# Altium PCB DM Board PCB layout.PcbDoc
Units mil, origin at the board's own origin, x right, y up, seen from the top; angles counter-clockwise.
Board outline 2298 x 2500 mil, 4 copper layers (Top Layer, InternalPlane1, InternalPlane2, Bottom Layer); 36 components, 42 nets, 176 pads, 73 vias.
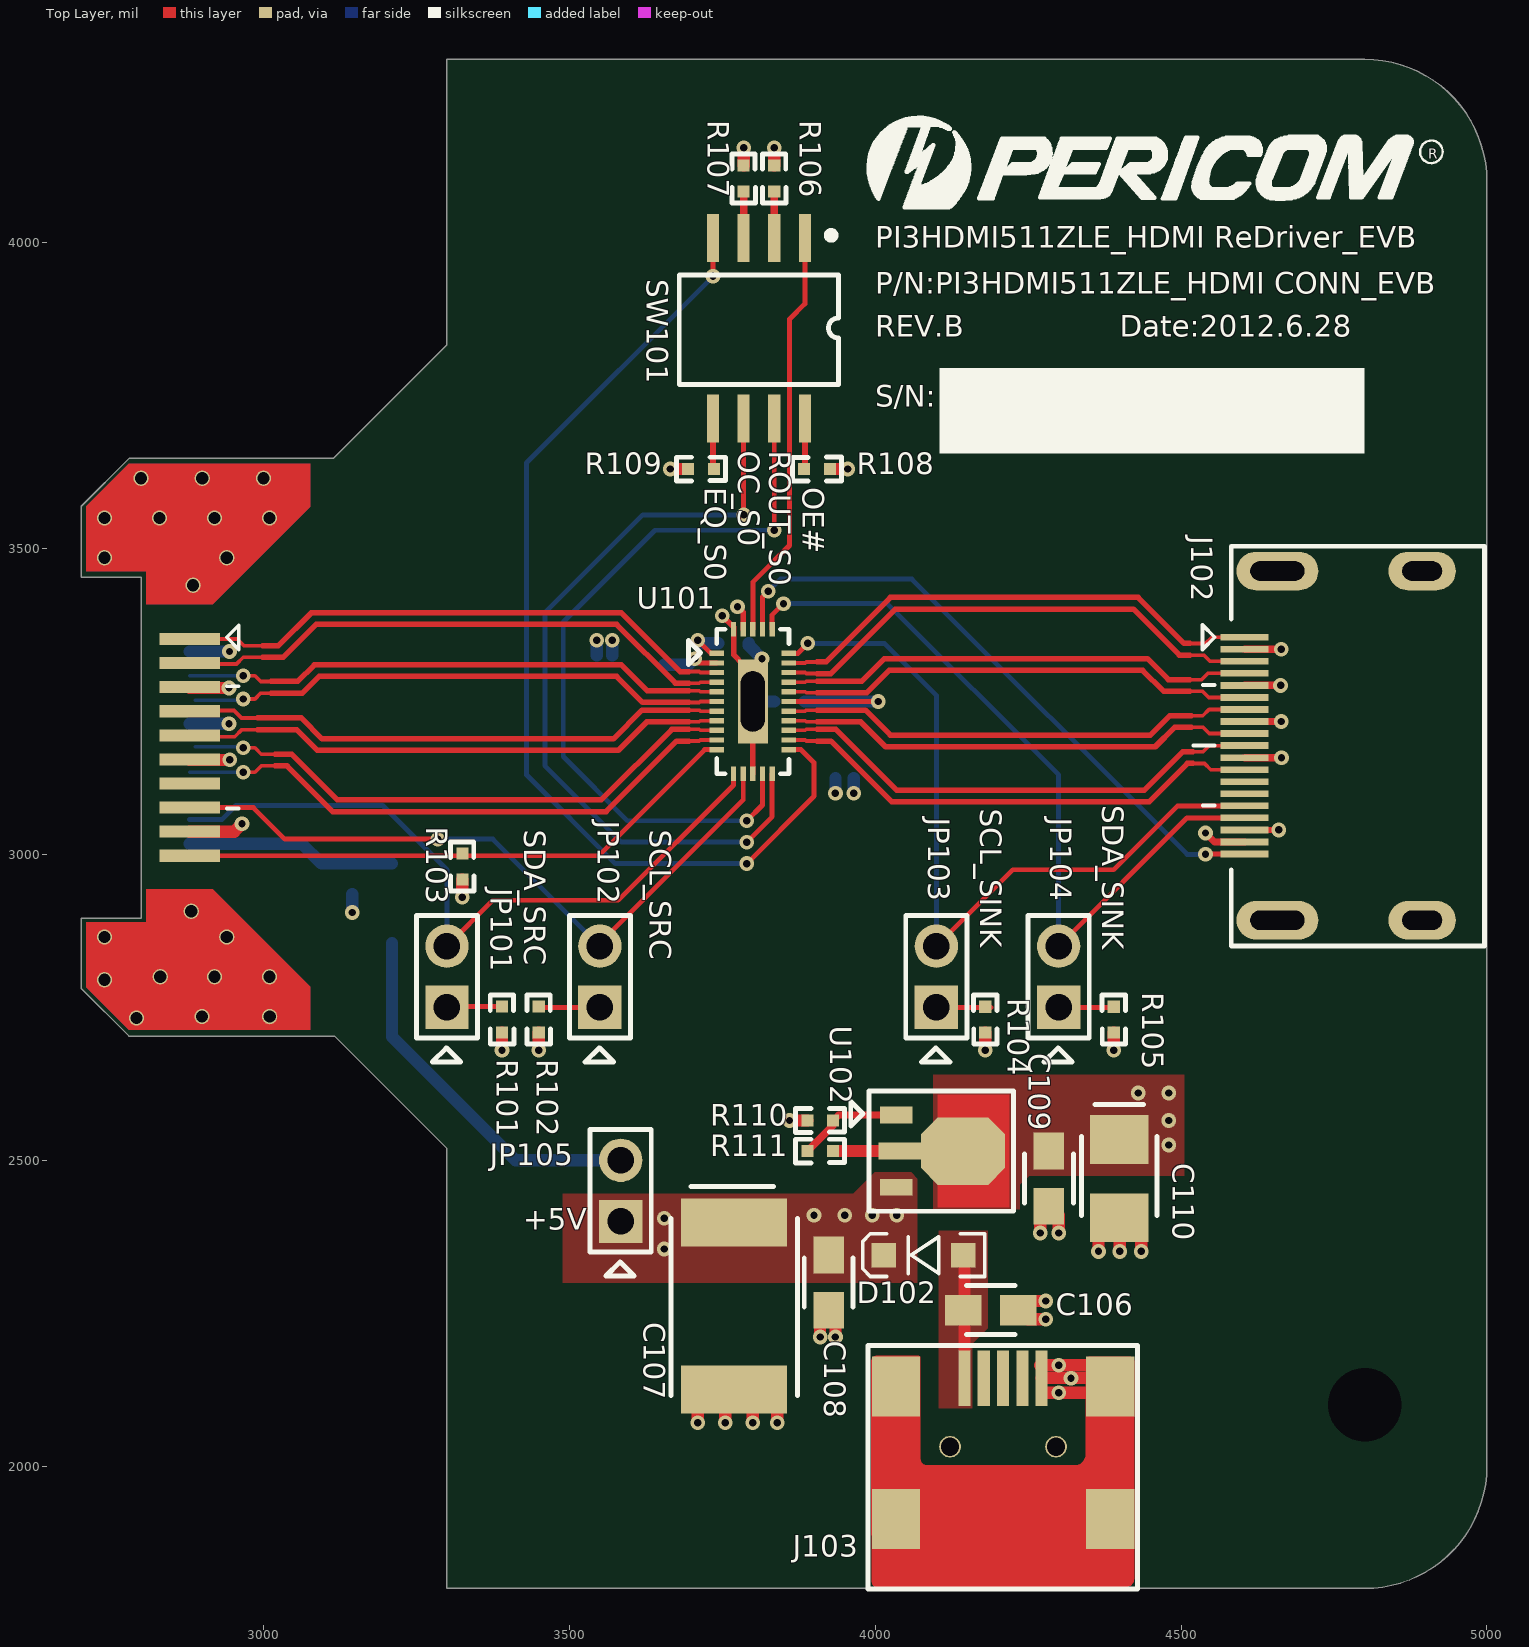
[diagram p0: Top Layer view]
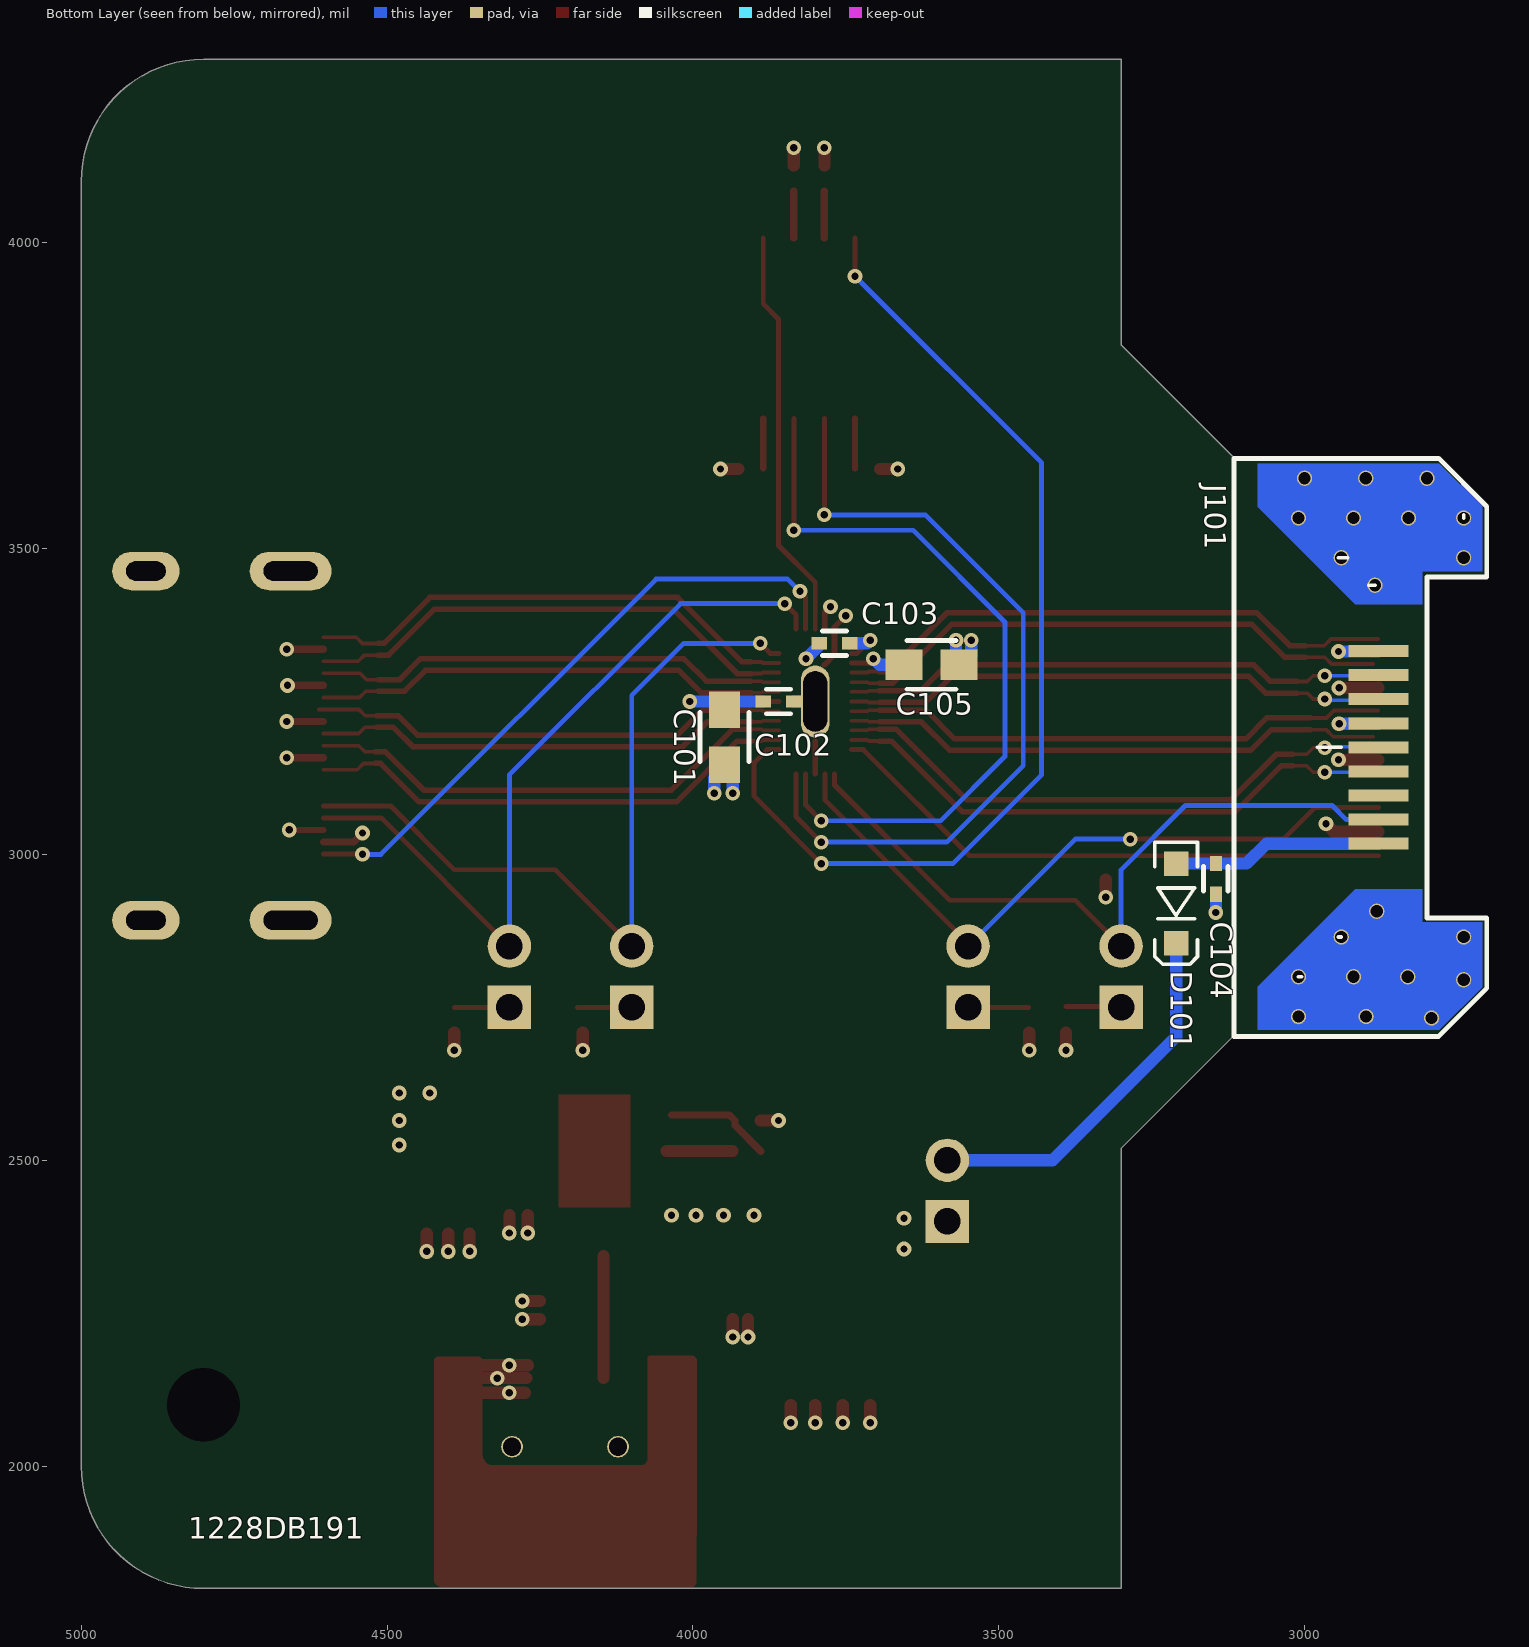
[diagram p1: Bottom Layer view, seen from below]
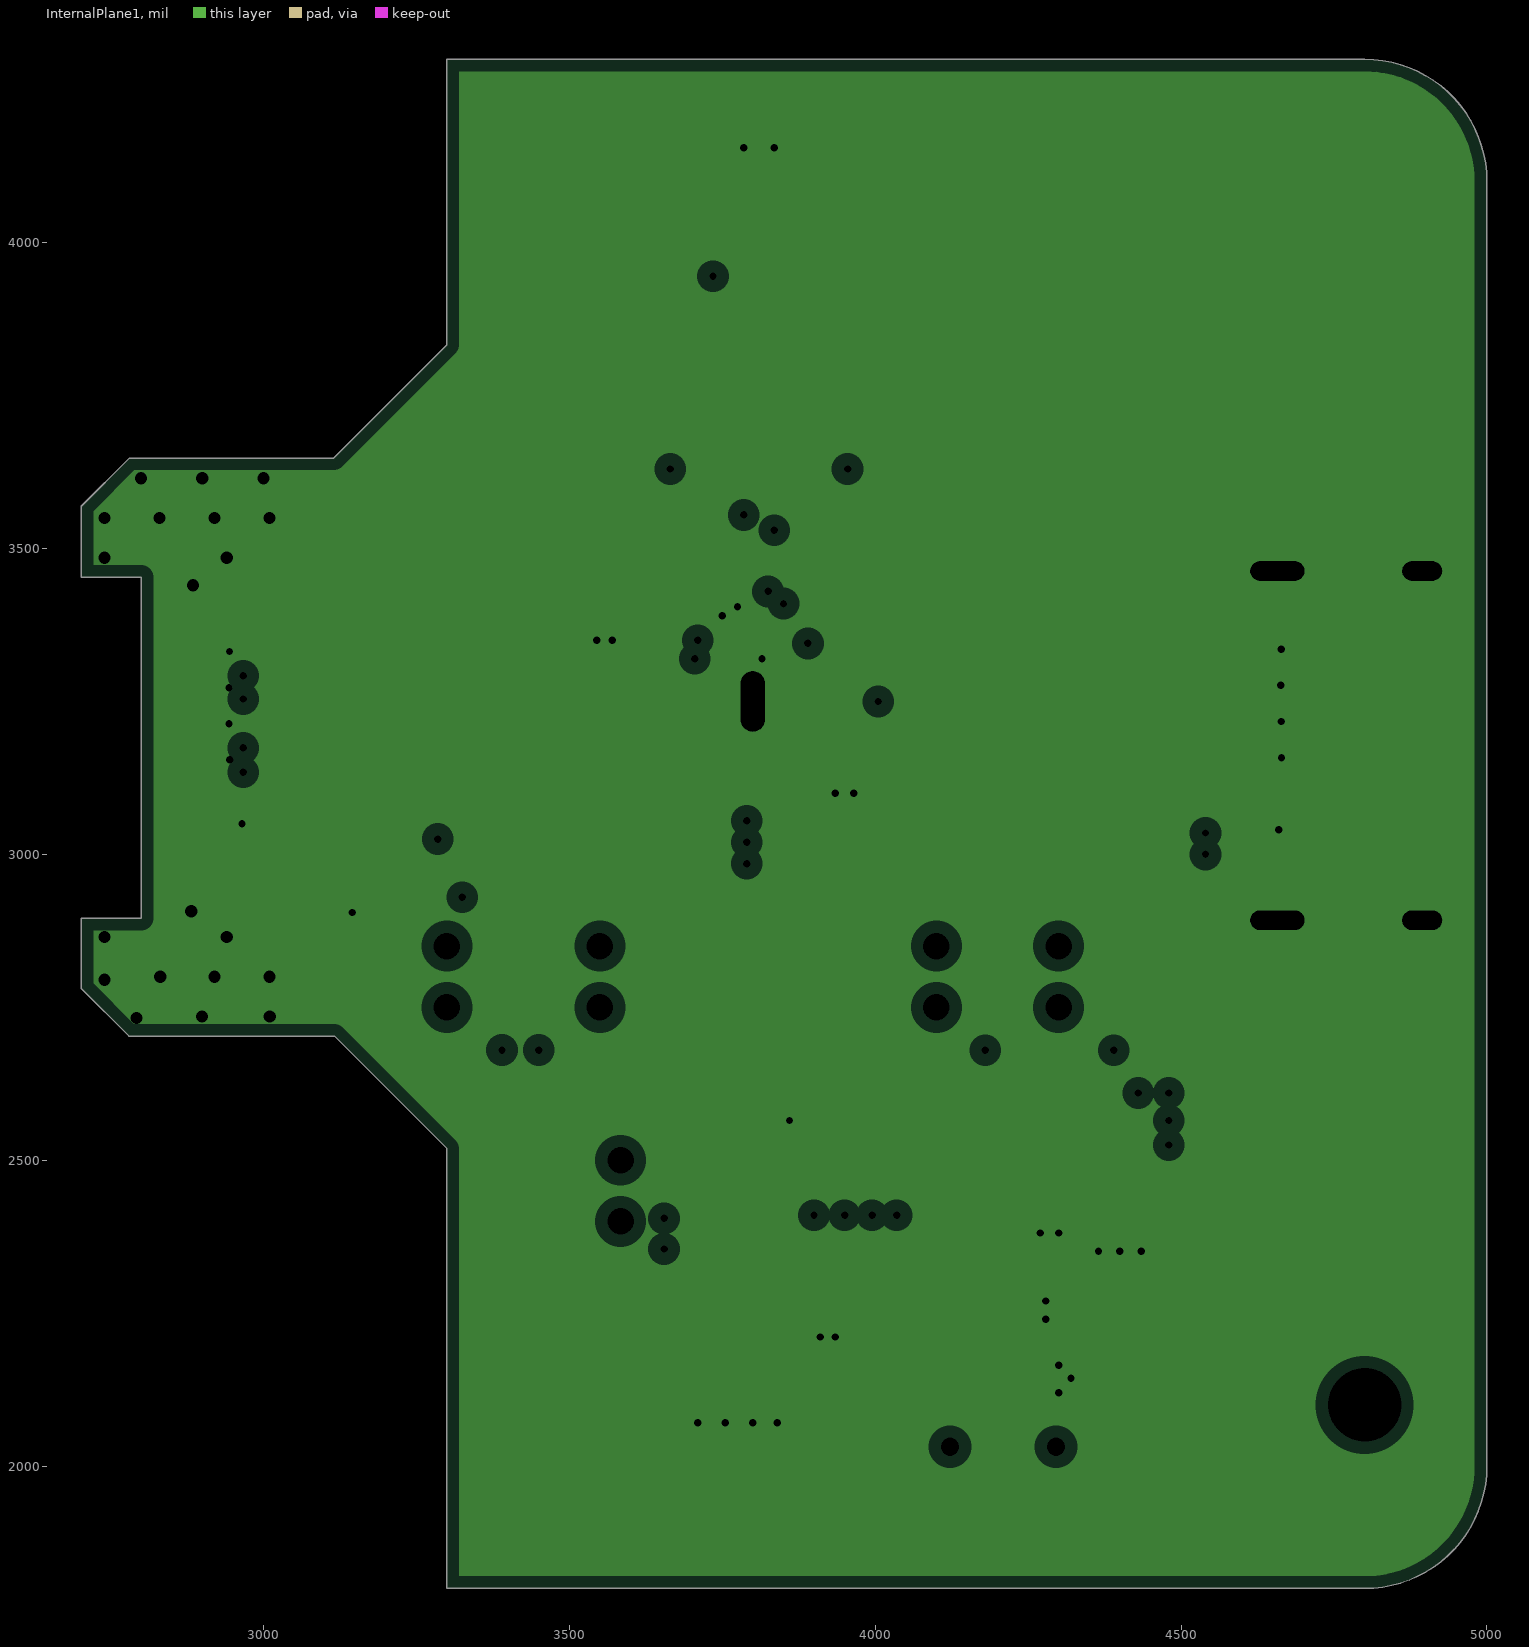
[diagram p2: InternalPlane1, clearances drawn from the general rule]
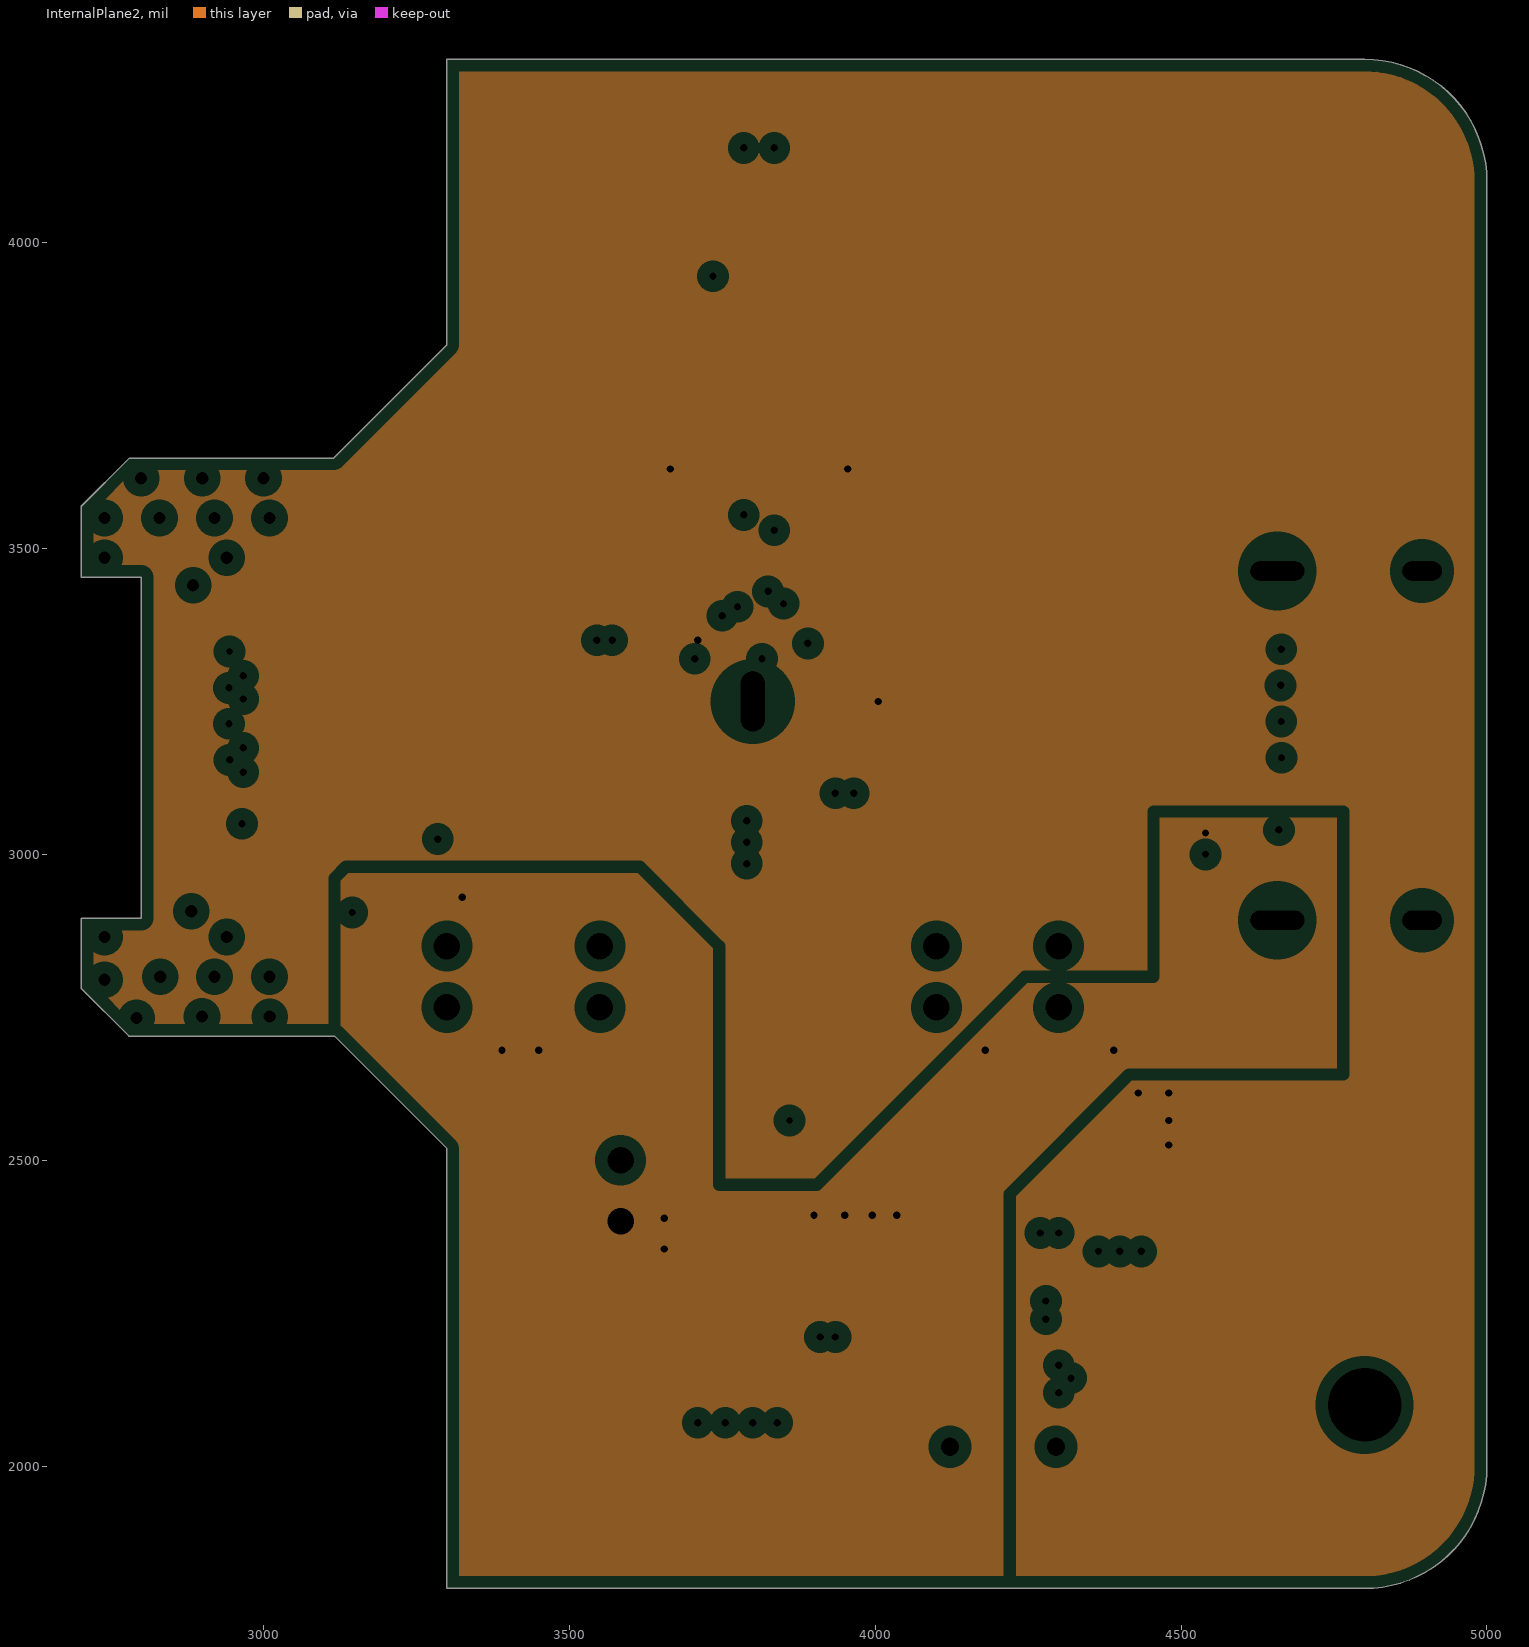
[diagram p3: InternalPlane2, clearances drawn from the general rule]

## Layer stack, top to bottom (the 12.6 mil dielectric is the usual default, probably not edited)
Top Layer: signal copper 1.4
Dielectric: core 12.6, FR-4, Dk 4.8
InternalPlane1: plane copper 1.4, net GND
Dielectric: prepreg 12.6, FR-4, Dk 4.8
InternalPlane2: plane copper 1.4, net (Multiple Nets)
Dielectric: core 12.6, FR-4, Dk 4.8
Bottom Layer: signal copper 1.4

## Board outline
2780,2703 2702,2781 2702,2896 2800,2896 2800,3453 2702,3453 2702,3569 2781,3648 3115,3648 3300,3833 3300,4300 4800,4300 cw(c4800,4100) 5000,4100 5000,2000 cw(c4800,2000) 4800,1800 3300,1800 3300,2519 3116,2703

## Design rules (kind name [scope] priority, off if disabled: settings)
Clearance [All] p1: gap=3
ComponentClearance [All] p1: gap=0 collisioncheckmode=3 verticalgap=0
DiffPairsRouting [All] p1: maxlimit=10 minlimit=10 mostfreqgap=10 maxuncoupledlength=500
HoleSize [All] p1: absolutevalues=TRUE maxlimit=500 minlimit=1 maxpercent=80.000 minpercent=20.000
PlaneClearance [All] p1: clearance=20
PlaneConnect [All] p1: planeconnectstyle=Direct reliefexpansion=20 reliefentries=4 reliefconductorwidth=10 reliefairgap=10
PolygonConnect [All] p1: connectstyle=Direct reliefconductorwidth=10 reliefentries=4 polygonreliefangle="90 Angle"
RoomDefinition "PI3HDMI511 EVB" [InComponentClass('PI3HDMI511 EVB')] p1: confinementstyle=ConfineIn formatcopy=TRUE lockcomponents=FALSE outline 15,185 17345,185 17345,7240 15,7240
RoutingVias [All] p1: holewidth=28 width=50 viastyle="Through Hole" minholewidth=8 minwidth=10 maxholewidth=28 maxwidth=50
SolderMaskExpansion [All] p1: expansion=4
TestPointUsage [All] p1: valid=0 allowmultiple=FALSE
Testpoint [All] p1: side=15 testpointundercomponent=TRUE minsize=40 maxsize=100 preferedsize=60 minholesize=0 maxholesize=40 preferedholesize=32 testpointgrid=1 style=1023 order=0123456789
Width [All] p1: maxlimit=150 minlimit=5 preferedwidth=10
14 further rules are at their usual default settings.

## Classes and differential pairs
component class "PI3HDMI511 EVB": C101 C102 C103 C104 C105 C106 C107 C108 C109 C110 D101 D102 J101 J102 J103 JP101 JP102 JP103 JP104 JP105 R101 R102 R103 R104 R105 R106 R107 R108 R109 R110 R111 SW101 U101 U102
differential pair NewDifferentialPair8: +OUT_D2- -OUT_D2+
differential pair NewDifferentialPair7: +OUT_D1- -OUT_D1+
differential pair NewDifferentialPair6: +OUT_D0- -OUT_D0+
differential pair NewDifferentialPair5: +OUT_CK- -OUT_CK+
differential pair NewDifferentialPair4: +IN_D2- -IN_D2+
differential pair NewDifferentialPair3: +IN_D1- -IN_D1+
differential pair NewDifferentialPair2: +IN_D0- -IN_D0+
differential pair NewDifferentialPair1: +IN_CK- -IN_CK+

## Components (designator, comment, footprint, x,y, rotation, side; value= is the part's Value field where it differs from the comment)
C101 "4.7u" CC_0805 3948.3,3191.7 r270 bottom
C102 "0.1u" CC_0402 3860,3250 r180 bottom
C103 "0.1u" CC_0402 3768.5,3345 r0 bottom
C104 "0.1u" CC_0402 3145,2960 r90 bottom
C105 "4.7u" CC_0805 3610,3310 r0 bottom
C106 "4.7u" CC_0805 4189,2255 r0 top
C107 "100u" CT_7343 3769,2280 r90 top
C108 "1u" CC_0805 3924,2300 r270 top
C109 "1u" CC_0805 4284,2470 r270 top
C110 "22u" CT_3528 4399,2470 r270 top
D101 "B0520LW" D@SOD-123 3210,2920 r270 bottom
D102 "B0520LW" D@SOD-123 4079,2345 r180 top
J101 "CON_HDMI_Plug" CON_HDMI_Plug 2840,3175 r0 bottom
J102 "CON_HDMI_Recept" CON_HDMI_Recept 4615,3355 r90 top
J103 "CON_USB2.0_MiniB_SMT" CON_USB2.0_MiniB_SMT 4209,1825 r90 top
JP101 "2x1 Pin Header" "2x1 Pin Header" 3300,2750 r90 top
JP102 "2x1 Pin Header" "2x1 Pin Header" 3550,2750 r90 top
JP103 "2x1 Pin Header" "2x1 Pin Header" 4100,2750 r90 top
JP104 "2x1 Pin Header" "2x1 Pin Header" 4300,2750 r90 top
JP105 "2x1 Pin Header" "2x1 Pin Header" 3584,2400 r90 top
R101 "47K" R_0402 3390,2730 r90 top
R102 "47K" R_0402 3450,2730 r90 top
R103 "4K7" R_0402 3325,2980 r90 top
R104 "2K2" R_0402 4180,2730 r270 top
R105 "2K2" R_0402 4390,2730 r270 top
R106 "4K7" R_0402 3835,4105 r90 top
R107 "4K7" R_0402 3785,4105 r90 top
R108 "4K7" R_0402 3905,3630 r180 top
R109 "4K7" R_0402 3715,3630 r0 top
R110 "0" RES@R_0402 3910,2565 r0 top
R111 "NP" RES@R_0402 3910,2515 r0 top
SW101 "SW_X4_Half_Pitch" SW_X4_Half_Pitch 3810,3860 r180 top
U101 "PI3HDMI511" TQFN32_3X6 3800,3250 r0 top locked
U102 "REG1117-3.3V" Pow_SOT_89 4089,2515 r270 top
? "" "Lable Hole" 4800,2100 r0 top
? "" PSC_LOG 4095,4160 r0 top

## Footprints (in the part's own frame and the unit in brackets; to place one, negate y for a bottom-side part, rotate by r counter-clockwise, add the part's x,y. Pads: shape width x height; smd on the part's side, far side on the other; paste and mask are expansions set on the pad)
"2x1 Pin Header" [mm] "Pin Header 2x1 Pitch 2.54mm"
  rect 1.8x1.8 hole 1.1: 1(0,0)
  round 1.8 hole 1.1: 2(2.54,0)
  silkscreen extent -2.27,-1.27 3.81,1.27
CC_0402 [mil]
  rect 25x20 smd: 1(-25,0) 2(25,0)
  silkscreen extent -20,-20 20,20
CC_0805 [mil]
  rect 60x50 smd: 1(-45,0) 2(45,0)
  silkscreen extent -40,-40 40,40
CON_HDMI_Plug [mm]
  rect 2.5x0.5 smd far side: 1(1,-4.5) 3(1,-3.5) 5(1,-2.5) 7(1,-1.5) 9(1,-0.5) 11(1,0.5) 13(1,1.5) 15(1,2.5) 17(1,3.5) 19(1,4.5)
  rect 2.5x0.5 smd: 2(1,-4) 4(1,-3) 6(1,-2) 8(1,-1) 10(1,0) 12(1,1) 14(1,2) 16(1,3) 18(1,4)
  round 0.635 hole 0.508: 20(-2.54,-9.525) 20(-2.54,-7.874) 20(-2.54,7.874) 20(-2.54,9.652) 20(-1.21,11.24) 20(-1.016,-11.176) 20(-0.254,-9.525) 20(-0.22,9.525) 20(1.067,6.807) 20(1.143,-6.731) 20(1.51,11.176) 20(1.524,-11.176) 20(2.032,-9.525) 20(2.032,9.525) 20(2.54,-7.874) 20(2.54,7.874) 20(4.064,-11.176) 20(4.318,-9.525) 20(4.318,9.525) 20(4.32,11.18)
  Top Layer region: -0.813,-5.944 1.968,-5.944 6.013,-9.989 6.013,-11.779 -1.517,-11.779 -1.524,-11.786 -3.302,-10.008 -3.302,-7.315 -0.813,-7.315
  Top Layer region: -0.813,5.893 1.968,5.893 6.013,9.938 6.013,11.728 -1.517,11.728 -1.524,11.735 -3.302,9.957 -3.302,7.264 -0.813,7.264
  Bottom Layer region: -0.813,-5.944 1.968,-5.944 6.013,-9.989 6.013,-11.779 -1.517,-11.779 -1.524,-11.786 -3.302,-10.008 -3.302,-7.315 -0.813,-7.315
  Bottom Layer region: -0.813,5.893 1.968,5.893 6.013,9.938 6.013,11.728 -1.517,11.728 -1.524,11.735 -3.302,9.957 -3.302,7.264 -0.813,7.264
  silkscreen extent -3.5,-12 7,12
CON_HDMI_Recept [mm]
  rect 0.28x2 smd: 1(0,0.281) 2(-0.5,0.281) 3(-1,0.281) 4(-1.5,0.281) 5(-2,0.281) 6(-2.5,0.281) 7(-3,0.281) 8(-3.5,0.281) 9(-4,0.281) 10(-4.5,0.281) 11(-5,0.281) 12(-5.5,0.281) 13(-6,0.281) 14(-6.5,0.281) 15(-7,0.281) 16(-7.5,0.281) 17(-8,0.281) 18(-8.5,0.281) 19(-9,0.281)
  oval 1.6x3.4 hole 0.8 slot 2.25 at 90 deg: 20(-11.75,-1.08) 21(2.75,-1.08)
  oval 1.6x2.8 hole 0.8 slot 1.65 at 90 deg: 22(-11.75,-7.09) 23(2.75,-7.09)
  silkscreen extent -12.82,-9.68 3.78,2.41
CON_USB2.0_MiniB_SMT [mm]
  rect 2.3x0.5 smd: 1(8.1,1.6) 2(8.1,0.8) 3(8.1,0) 4(8.1,-0.8) 5(8.1,-1.6)
  rect 2.5x2 smd: 5(2.25,4.45) 5(2.25,-4.45) 5(7.75,-4.45) 5(7.75,4.45)
  round 0.9 hole 0.762 unplated: 10(5.25,-2.2) 11(5.25,2.2)
  Top Layer region: 1.58,5.45 -0.35,5.45 -0.438,5.432 -0.513,5.383 -0.562,5.308 -0.58,5.22 -0.58,5.22 -0.58,-5.09 -0.553,-5.224 -0.477,-5.337 -0.364,-5.413 -0.23,-5.44 -0.23,-5.44 8.81,-5.44 8.875,-5.427 8.93,-5.39 8.967,-5.335 8.98,-5.27 8.98,-5.27 8.98,-3.59 8.968,-3.529 8.933,-3.477 8.881,-3.442 8.82,-3.43 8.82,-3.43 4.93,-3.43 4.758,-3.396 4.612,-3.298 4.514,-3.152 4.48,-2.98 4.48,-2.98 4.48,3.17 4.5,3.269 4.556,3.354 4.641,3.41 4.74,3.43 4.74,3.43 8.93,3.43 8.964,3.437 8.994,3.456 9.013,3.486 9.02,3.52 9.02,3.52 9.02,5.26 9.004,5.34 8.958,5.408 8.89,5.454 8.81,5.47 8.81,5.47 1.6,5.47 1.592,5.468 1.586,5.464 1.582,5.458 1.58,5.45
  silkscreen extent -0.65,-5.59 9.45,5.6
CT_3528 [mil]
  rect 80x95 smd: 1(-64,0) 2(64,0)
  silkscreen extent -121,-62 60,62
CT_7343 [mm]
  rect 2x4.4 smd: 1(3,0) 2(-3.926,-0.011)
  silkscreen extent -4.19,-2.64 4.5,2.62
D@SOD-123 [mil]
  rect 40x40 smd: 1(-65,0) 2(65,0)
  silkscreen extent -100,-35 100,35
"Lable Hole" [mil]
  round 0 hole 120 unplated: ""(0,0)
Pow_SOT_89 [mm] "SOT-89; Body 4.6 x 4.25 mm, inc. leads (LxW max)"
  rect 0.7x1.35 smd: 1(-1.5,-1.388) 3(1.5,-1.388)
  oct 2.8x3.5 smd: 2(0,1.388)
  rect 0.7x1.9 smd: 2(0,-1.163)
  Top Layer region: -2.346,0.336 -2.346,3.302 2.322,3.302 2.323,3.303 2.323,0.338 2.325,0.336
  silkscreen extent -2.5,-3.28 2.5,3.49
PSC_LOG [mil]
  silkscreen extent -107,-103 833,45
R_0402 [mm]
  rect 0.5x0.5 smd: 1(-0.532,-0.001) 2(0.54,-0.001)
  silkscreen extent -1.02,-0.49 1.02,0.49
RES@R_0402 [mm]
  rect 0.5x0.5 smd: 1(-0.532,-0.001) 2(0.54,-0.001)
  silkscreen extent -1.02,-0.49 1.02,0.49
SW_X4_Half_Pitch [mm]
  rect 0.5x2 smd: 1(-1.905,-3.75) 2(-0.635,-3.75) 3(0.635,-3.75) 4(1.905,-3.75) 5(1.905,3.75) 6(0.635,3.75) 7(-0.635,3.75) 8(-1.905,3.75)
  silkscreen extent -3.31,-4.01 3.31,2.34
TQFN32_3X6 [mm]
  rect 0.6x0.22 smd: 1(-1.5,2) 2(-1.5,1.6) 3(-1.5,1.2) 4(-1.5,0.8) 5(-1.5,0.4) 6(-1.5,0) 7(-1.5,-0.4) 8(-1.5,-0.8) 9(-1.5,-1.2) 10(-1.5,-1.6) 11(-1.5,-2) 17(1.5,-2) 18(1.5,-1.6) 19(1.5,-1.2) 20(1.5,-0.8) 21(1.5,-0.4) 22(1.5,0) 23(1.5,0.4) 24(1.5,0.8) 25(1.5,1.2) 26(1.5,1.6) 27(1.5,2)
  rect 0.22x0.6 smd: 12(-0.8,-3) 13(-0.4,-3) 14(0,-3) 15(0.4,-3) 16(0.8,-3) 28(0.8,3) 29(0.4,3) 30(0,3) 31(-0.4,3) 32(-0.8,3)
  rect 1.25x3.5 smd: 33(0,0)
  oval 1.2x3 hole 1 slot 2.5 at 90 deg: 33(0,0)
  silkscreen extent -2.67,-3 1.5,3

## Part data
C101 C102 C103: library part C_0.1u_0402
C104: library part C_10n_0402
C105: library part C_4.7u_0805
C106 C108 C109: library part "CHIP CAP0805"
C107: library part "100UF 7343_1"
C110: library part "22UF 3528"
D101 D102: library part SchottkyDiode@SOD-123_1
R101 R102 R103 R104 R105 R106 R107 R108 R109: library part R_0402
R110 R111: library part "CHIP RES0402_1"
U101: library part PI3VDP411LSZDE@TQFN48_4
U102: library part REG1117ADJ@SOT89

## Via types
v1: diameter 24, hole 12, Top Layer to Bottom Layer, tented both sides, 73 vias

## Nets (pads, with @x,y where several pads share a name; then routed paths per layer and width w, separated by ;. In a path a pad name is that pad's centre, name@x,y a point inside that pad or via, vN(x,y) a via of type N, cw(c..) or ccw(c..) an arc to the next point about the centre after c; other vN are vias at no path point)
+3V3: C101.1 C102.1 C103.1 C109.1 C110.1 R108.1 R109.1 R111.2 U101.1 U101.22 U102.2 | length 507.1
  Top Layer w8: v1(3710,3350) 3731.26,3328.74 U101.1 ; U101.22 v1(4005,3250)
  Top Layer w20: v1(3665.03,3629.97) R109.1 ; R108.1 v1(3954.97,3630.03) ; R111.2@3935.24,2515 U102.2@4043.21,2515
  Bottom Layer w20: v1@3710.2,3350 3715.2,3345 C103.1 ; C102.1 v1(4005,3250)
  other v1: 4480,2525 4480,2565 4430,2610 4480,2610
+5V: C107.1 C108.1 D102.2 J102.18 JP105.1 R101.1 R102.1 R103.1 R104.2 R105.2 U102.3 | length 215.1
  Top Layer w12: v1(4540,3035) 4554.65,3020.35 J102.18
  Top Layer w20: v1(3325.03,2930.03) R103.1 ; v1(3390.03,2680.03) R101.1 ; v1(3450.03,2680.03) R102.1 ; v1(4179.97,2679.72) R104.2 ; v1(4389.97,2679.72) R105.2
  other v1: 3655,2355 3655,2405 3900,2410 3950,2410 3995,2410 4035,2410
+5V_A: C104.2 D101.1 J101.18 | length 344.1
  Bottom Layer w20: J101.18 3062.48,3017.52 3095,2985 D101.1
+5V_USB: C106.1 D102.1 J103.1 | length 199.1
  Top Layer w20: J103.1 D102.1@4146.01,2342.99
/OE: SW101.1 U101.30 | length 674.7
  Top Layer w8: U101.30 3800,3445 3860,3505 3860,3875 3885,3900 SW101.1
EQ_S0: SW101.4 U101.17 | length 1684.3
  Top Layer w8: v1(3735,3945) SW101.4 ; v1(3790,2985) 3900,3095 3900,3150 3878.74,3171.26 U101.17
  Bottom Layer w8: v1(3735,3945) 3430,3640 3430,3130 3575,2985 v1(3790,2985)
GND: C101.2 C102.2 C103.2 C104.1 C105.1 C106.2 C107.2 C108.2 C109.2 C110.2 J101.2 J101.5 J101.8 J101.11 J101.17 J101.20 J102.2 J102.5 J102.8 J102.11 J102.17 J102.20 J102.21 J102.22 J102.23 J103.5 R106.2 R107.2 R110.1 U101.14 U101.31 U101.32 U101.33 | length 1726.7
  Top Layer w9: v1(3750,3390) 3768.5,3371.5 3768.5,3326.5 U101.33@3785,3310 ; v1(3775,3405) 3784.25,3395.75 U101.31 ; U101.14 U101.33@3800,3185
  Top Layer w10: J102.17 v1(4659.96,3040.04)
  Top Layer w12: J102.11 v1(4664.15,3158.15) ; J102.8 v1(4663.8,3217.2) ; J102.5 v1(4662.74,3276.26) ; J102.2 v1(4663.69,3335.32)
  Top Layer w20: J101.17 2952.2,3037.2 v1(2965,3050) ; J101.11@2879.37,3154.48 v1(2944.68,3154.48) ; J101.5@2879.37,3272.59 v1@2943,3272.17 ; v1(3710,2070.98) C107.2@3710,2100 ; v1(3755,2070.98) C107.2@3755,2100 ; R107.2 v1(3785.03,4154.97) ; v1(3800,2070.98) C107.2@3800,2100 ; R106.2 v1(3835.03,4154.97) ; v1(3840,2070.98) C107.2@3840,2100 ; v1(3860.03,2564.97) R110.1 ; v1(3910,2210.98) C108.2@3910,2240 ; v1(3935,2210.98) C108.2@3935,2240 ; C106.2@4250,2240 v1(4279.02,2240) ; C106.2@4250,2270 v1(4279.02,2270) ; J103.5@4270,2165 J103.5@4355,2165 ; v1(4270,2380.98) C109.2@4270,2410 ; J103.5@4271.99,2143.9 J103.5@4353.9,2143.9 ; J103.5@4275,2120 J103.5@4360,2120 ; v1(4300,2380.98) C109.2@4300,2410 ; v1(4365,2350.98) C110.2@4365,2380 ; v1(4400,2350.98) C110.2@4400,2380 ; v1(4435,2350.98) C110.2@4435,2380
  Bottom Layer w20: J101.8@2879.37,3213.54 v1(2943.63,3213.54) ; J101.2@2879.37,3331.65 v1(2944.48,3331.65) ; v1(3145,2905) C104.1 ; C105.1@3545,3325 v1(3545,3350) ; C105.1@3570,3325 v1(3570,3350) ; C103.2 3793.5,3341.5 v1(3815,3320) ; U101.33@3820,3250 C102.2 ; v1(3935,3100) C101.2@3935,3125 ; v1(3965,3100) C101.2@3965,3125
  other v1: 4300,2120 4320,2143.9 4300,2165 2943.63,3272.16
HPD_SINK: J102.19 U101.29 | length 1038.7
  Top Layer w8: U101.29 3815.75,3420.75 v1(3825,3430) ; v1@4540.67,3000.67 J102.19
  Bottom Layer w8: v1(3825,3430) 3845,3450 4060,3450 4510,3000 v1(4540,3000)
HPD_SRC: J101.19 R103.2 U101.11 | length 933.4
  Top Layer w8: J101.19 3547.83,2997.83 3721.26,3171.26 U101.11
IN_CK+: J101.10 U101.9 | length 936.5
  Top Layer w6: v1(2967,3174.17) 2986,3174.17 2996.5,3163.67 3019,3163.67 ; 3695.1,3204.38 3712.51,3204.38 3714.13,3202.76 U101.9
  Top Layer w9: 3019,3163.67 3046.33,3163.67 3121,3089 3552.13,3089 3667.51,3204.38 3695.1,3204.38
  Bottom Layer w6: J101.10@2889,3176.17 2965,3176.17 v1(2967,3174.17)
IN_CK-: J101.12 U101.10 | length 943.7
  Top Layer w6: v1(2967,3134.17) 2986,3134.17 2996.5,3144.67 3018,3144.67 ; 3694.92,3185.38 3712.51,3185.38 3714.13,3187.01 U101.10
  Top Layer w9: 3019,3144.67 3038.46,3144.67 3113.13,3070 3560,3070 3675.38,3185.38 3694.92,3185.38
  Bottom Layer w6: J101.12@2880,3134.17 v1(2967,3134.17)
IN_D0+: J101.7 U101.7 | length 900.8
  Top Layer w6: J101.7@2879.37,3235.17 2952,3235.17 2964.13,3223.04 2991,3223.04 ; 3695.1,3235.88 3712.51,3235.88 3714.13,3234.25 U101.7
  Top Layer w9: 2991,3223.04 3061.96,3223.04 3096,3189 3572.13,3189 3619.01,3235.88 3695.1,3235.88
IN_D0-: J101.9 U101.8 | length 894.1
  Top Layer w6: J101.9@2888,3192.17 2953,3192.17 2964.87,3204.04 2993,3204.04 ; 3694.92,3216.88 3712.51,3216.88 3714.13,3218.5 U101.8
  Top Layer w9: 2991,3204.04 3054.09,3204.04 3088.13,3170 3580,3170 3626.88,3216.88 3694.92,3216.88
IN_D1+: J101.4 U101.5 | length 895.2
  Top Layer w6: v1(2967,3292.17) 2986,3292.17 2995.5,3282.67 3013,3282.67 ; 3695.1,3267.37 3712.51,3267.37 3714.13,3265.75 U101.5
  Top Layer w9: 3013,3282.67 3055.8,3282.67 3083.13,3310 3585,3310 3627.63,3267.37 3695.1,3267.37
  Bottom Layer w6: J101.4@2879.37,3292.28 2879.48,3292.17 v1(2967,3292.17)
IN_D1-: J101.6 U101.6 | length 885.4
  Top Layer w6: v1(2967,3254.17) 2986,3254.17 2995.5,3263.67 3012,3263.67 ; 3694.92,3248.37 3712.51,3248.37 3714.13,3250 U101.6
  Top Layer w9: 3013,3263.67 3063.67,3263.67 3091,3291 3577.13,3291 3619.76,3248.37 3694.92,3248.37
  Bottom Layer w6: J101.6@2889,3252.17 2965,3252.17 v1(2967,3254.17)
IN_D2+: J101.1 U101.3 | length 928.9
  Top Layer w6: J101.1 2956.98,3352.17 2968,3341.15 2999,3341.15 ; 3695.1,3298.87 3712.51,3298.87 3714.13,3297.24 U101.3
  Top Layer w9: 2999,3341.15 3024.28,3341.15 3078.13,3395 3585,3395 3681.13,3298.87 3695.1,3298.87
IN_D2-: J101.3 U101.4 | length 920.3
  Top Layer w6: J101.3@2888,3311.17 2956.02,3311.17 2967,3322.15 2999,3322.15 ; 3694.92,3279.87 3712.51,3279.87 3714.13,3281.5 U101.4
  Top Layer w9: 2999,3322.15 3032.15,3322.15 3086,3376 3577.13,3376 3673.26,3279.87 3694.92,3279.87
NetC105_2: C105.2 U101.2 | length 93
  Top Layer w8: v1(3705,3320) 3712.01,3312.99 U101.2
  Bottom Layer w20: C105.2 3695,3310 v1(3705,3320)
NetD101_2: D101.2 JP105.2 | length 610.7
  Bottom Layer w20: D101.2 3210,2702 3412,2500 JP105.2
NetJP101_2: JP101.1 R101.2 | length 88.8
  Top Layer w8: JP101.1@3301.27,2751.27 R101.2
NetJP102_2: JP102.1 R102.2 | length 98.7
  Top Layer w8: R102.2@3451.3,2750 JP102.1
NetJP103_1: JP103.1 R104.1 | length 89
  Top Layer w8: JP103.1 R104.1@4189.02,2750
NetJP104_1: JP104.1 R105.1 | length 90
  Top Layer w8: JP104.1 R105.1@4389.97,2750
NetR106_1: R106.1 SW101.2 | length 76.4
  Top Layer w12: SW101.2 R106.1
NetR107_1: R107.1 SW101.3 | length 76.4
  Top Layer w12: SW101.3 R107.1
NetR108_2: R108.2 SW101.8 | length 81.1
  Top Layer w10: R108.2@3885,3631.3 SW101.8
NetR109_2: R109.2 SW101.5 | length 81.1
  Top Layer w10: R109.2@3735,3631.24 SW101.5
NetR110_2: R110.2 R111.1 U102.1 | length 174.4
  Top Layer w12: R111.1 3931.27,2557.19 R110.2 3940.35,2574.06 U102.1
OC_S0: SW101.6 U101.16 | length 1309.5
  Top Layer w8: v1(3785,3555) SW101.6 ; v1(3790,3020) 3831.5,3061.5 U101.16
  Bottom Layer w8: v1(3785,3555) 3620,3555 3460,3395 3460,3145 3585,3020 v1(3790,3020)
OUT_CK+: J102.10 U101.19 | length 816.9
  Top Layer w6: U101.19 3885.87,3202.76 3887.49,3204.38 3905.08,3204.38 ; 4519,3167.65 4536,3167.65 4546.18,3177.83 J102.10
  Top Layer w9: 3905.08,3204.38 3935.62,3204.38 4035,3105 4440,3105 4502.65,3167.65 4519,3167.65
OUT_CK-: J102.12 U101.18 | length 815.9
  Top Layer w6: U101.18 3885.87,3187.01 3887.49,3185.38 3904.9,3185.38 ; 4520,3148.65 4538.35,3148.65 4548.54,3138.46 J102.12
  Top Layer w9: 3904.9,3185.38 3927.75,3185.38 4027.13,3086 4447.87,3086 4510.52,3148.65 4519,3148.65
OUT_D0+: J102.7 U101.21 | length 787
  Top Layer w6: U101.21 3885.87,3234.25 3887.49,3235.88 3905.08,3235.88 ; 4517,3226.7 4535.7,3226.7 4545.89,3236.89 J102.7@4611.11,3236.89
  Top Layer w9: 3905.08,3235.88 3984.12,3235.88 4025,3195 4450,3195 4481.7,3226.7 4517,3226.7
OUT_D0-: J102.9 U101.20 | length 780.8
  Top Layer w6: U101.20 3885.87,3218.5 3887.49,3216.88 3904.9,3216.88 ; 4516,3207.7 4536,3207.7 4546.19,3197.52 J102.9
  Top Layer w9: 3904.9,3216.88 3976.25,3216.88 4017.13,3176 4457.87,3176 4489.57,3207.71 4517,3207.71
OUT_D1+: J102.4 U101.24 | length 779.2
  Top Layer w6: U101.24 3885.87,3281.5 3887.49,3283.12 3905.08,3283.12 ; 4514,3285.76 4534,3285.76 4544.19,3295.94 J102.4
  Top Layer w9: 3905.08,3283.12 3978.12,3283.12 4015,3320 4445,3320 4479.24,3285.76 4514,3285.76
OUT_D1-: J102.6 U101.23 | length 779.2
  Top Layer w6: U101.23 3885.87,3265.75 3887.49,3264.12 3904.9,3264.12 ; 4514,3266.76 4535,3266.76 4545.18,3256.57 J102.6
  Top Layer w9: 3904.9,3264.12 3985.99,3264.12 4022.87,3301 4437.13,3301 4471.37,3266.76 4514,3266.76
OUT_D2+: J102.1 U101.26 | length 824.6
  Top Layer w6: U101.26 3885.87,3312.99 3887.49,3314.62 3905.08,3314.62 ; 4514,3344.82 4540,3344.82 4550.18,3355 J102.1
  Top Layer w9: 3905.08,3314.62 3919.62,3314.62 4025,3420 4430,3420 4505.18,3344.82 4514,3344.82
OUT_D2-: J102.3 U101.25 | length 824.6
  Top Layer w6: U101.25 3885.87,3297.24 3887.49,3295.62 3904.9,3295.62 ; 4514,3325.81 4537,3325.81 4547.19,3315.63 J102.3
  Top Layer w9: 3904.9,3295.62 3927.49,3295.62 4032.87,3401 4422.13,3401 4497.31,3325.82 4514,3325.82
ROUT_S0: SW101.7 U101.15 | length 1240.5
  Top Layer w8: v1(3790,3055) 3815.75,3080.75 U101.15 ; v1(3835,3530) SW101.7
  Bottom Layer w8: v1(3790,3055) 3595,3055 3490,3160 3490,3380 3640,3530 v1(3835,3530)
SCL_SINK: J102.15 JP103.2 U101.27 | length 1291.8
  Top Layer w8: U101.27 3873.74,3328.74 v1(3890,3345) ; JP103.2 4225,2975 4390,2975 4494.41,3079.41 J102.15
  Bottom Layer w8: v1(3890,3345) 4015,3345 4100,3260 JP103.2
SCL_SRC: J101.15 JP102.2 U101.13 | length 1141.9
  Top Layer w8: J101.15 2983.43,3076.57 3035,3025 v1(3285,3025) ; JP102.2@3547.5,2852.5 3784.25,3089.25 U101.13
  Bottom Layer w8: v1(3285,3025) 3375,3025 JP102.2
SDA_SINK: J102.16 JP104.2 U101.28 | length 1286.3
  Top Layer w8: U101.28 3831.5,3391.5 v1(3850,3410) ; JP104.2 4509.72,3059.72 J102.16
  Bottom Layer w8: v1(3850,3410) 4020,3410 4300,3130 JP104.2
SDA_SRC: J101.16 JP101.2 U101.12 | length 1194.7
  Top Layer w8: JP101.2 3375,2925 3580,2925 3768.5,3113.5 U101.12
  Bottom Layer w8: J101.16 2931.89,3056.89 2955,3080 3195,3080 3300,2975 JP101.2
pads on no net: ?. J101.13 J101.14 J102.13 J102.14 J103.2 J103.3 J103.4 J103.10 J103.11

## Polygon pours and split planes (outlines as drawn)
+3V3 on Top Layer "MidLayer1-No Net" (solid, remove dead copper, pour order 1002): 4095,2640 4505,2640 4505,2475 4251.91,2475 4236.73,2460 4236.73,2420 4095,2420 4095,2640
+5V on Top Layer "MidLayer1-No Net" (solid, remove dead copper, pour order 1001): 3999,2480 4059,2480 4069,2470 4069,2300 3489,2300 3489,2445 3964,2445 3999,2480
+5V_USB on Top Layer "MidLayer1-No Net" (solid, remove dead copper, pour order 1000): 4159,2095 4104,2095 4104,2385 4184,2385 4184,2225 4159,2200 4159,2095
GND on InternalPlane1 (split plane): 4823.48,4278.35 4846.56,4273.76 4868.84,4266.19 4889.94,4255.78 4909.51,4242.71 4927.2,4227.2 4942.71,4209.51 4955.79,4189.94 4966.19,4168.84 4973.76,4146.56 4978.35,4123.48 4979.82,4101.05 4979.61,4100 4979.61,2000 4979.82,1998.95 4978.35,1976.52 4973.76,1953.44 4966.19,1931.16 4955.78,1910.06 4942.71,1890.49 4927.2,1872.8 4909.51,1857.29 4889.94,1844.21 4868.84,1833.81 4846.56,1826.24 4823.48,1821.65 4801.05,1820.18 4800,1820.39 3320.39,1820.39 3320.39,2519 3318.84,2526.8 3314.42,2533.42 3130.42,2717.42 3123.8,2721.84 3116,2723.39 2788.45,2723.39 2722.39,2789.45 2722.39,2875.61 2800,2875.61 2807.8,2877.16 2814.42,2881.58 2818.84,2888.2 2820.39,2896 2820.39,3453 2818.84,3460.8 2814.42,3467.42 2807.8,3471.84 2800,3473.39 2722.39,3473.39 2722.39,3560.55 2789.45,3627.61 3115,3627.61 3122.8,3629.16 3129.42,3633.58 3314.42,3818.58 3318.84,3825.2 3320.39,3833 3320.39,4279.61 4800,4279.61 4801.05,4279.82
+5V on InternalPlane2 (split plane): 4754.8,2650.2 4415,2650.2 4411.1,2649.42 4407.79,2647.21 4212.79,2452.21 4210.58,2448.9 4209.8,2445 4209.8,1820.39 3320.39,1820.39 3320.39,2519 3318.84,2526.8 3314.42,2533.42 3130.42,2717.42 3126.2,2720.24 3126.2,2956.78 3139.22,2969.8 3610.78,2969.8 3734.8,2845.78 3734.8,2460 3735.58,2456.1 3737.79,2452.79 3741.1,2450.58 3745,2449.8 3905,2449.8 3908.9,2450.58 3912.21,2452.79 4249.22,2789.8 4455,2789.8 4458.9,2790.58 4462.21,2792.79 4464.42,2796.1 4465.2,2800 4465.2,3059.8 4754.8,3059.8
+3V3 on InternalPlane2 (split plane): 4823.48,4278.35 4846.56,4273.76 4868.84,4266.19 4889.94,4255.78 4909.51,4242.71 4927.2,4227.2 4942.71,4209.51 4955.79,4189.94 4966.19,4168.84 4973.76,4146.56 4978.35,4123.48 4979.82,4101.05 4979.61,4100 4979.61,2000 4979.82,1998.95 4978.35,1976.52 4973.76,1953.44 4966.19,1931.16 4955.78,1910.06 4942.71,1890.49 4927.2,1872.8 4909.51,1857.29 4889.94,1844.21 4868.84,1833.81 4846.56,1826.24 4823.48,1821.65 4801.05,1820.18 4800,1820.39 4230.2,1820.39 4230.2,2440.78 4419.22,2629.8 4765,2629.8 4768.9,2630.58 4772.21,2632.79 4774.42,2636.1 4775.2,2640 4775.2,3070 4774.42,3073.9 4772.21,3077.21 4768.9,3079.42 4765,3080.2 4455,3080.2 4451.1,3079.42 4447.79,3077.21 4445.58,3073.9 4444.8,3070 4444.8,2810.2 4245,2810.2 4241.1,2809.42 4237.79,2807.21 3900.78,2470.2 3755.2,2470.2 3755.2,2850 3754.42,2853.9 3752.21,2857.21 3622.21,2987.21 3618.9,2989.42 3615,2990.2 3135,2990.2 3131.1,2989.42 3127.79,2987.21 3108.79,2968.21 3106.58,2964.9 3105.8,2961 3105.8,2723.39 2788.45,2723.39 2722.39,2789.45 2722.39,2875.61 2800,2875.61 2807.8,2877.16 2814.42,2881.58 2818.84,2888.2 2820.39,2896 2820.39,3453 2818.84,3460.8 2814.42,3467.42 2807.8,3471.84 2800,3473.39 2722.39,3473.39 2722.39,3560.55 2789.45,3627.61 3115,3627.61 3122.8,3629.16 3129.42,3633.58 3314.42,3818.58 3318.84,3825.2 3320.39,3833 3320.39,4279.61 4800,4279.61 4801.05,4279.82

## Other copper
Top Layer:
  text "TOP LAYER" at 6041,1991 h80
  text "1" at 6691,1861 h80
Bottom Layer:
  text "BOTTOM LAYER" at 6041,1991 h80
  text "4" at 6691,1861 h80
InternalPlane1 (plane layer: these items are gaps in the copper):
  text "POWER PLANE LAYER" at 6041,1991 h80
  text "2" at 6691,1861 h80
InternalPlane2 (plane layer: these items are gaps in the copper):
  lines w20: 3116,2703 3116,2961 3135,2980 3615,2980 3745,2850 3745,2460 3905,2460 4245,2800 4455,2800 4455,3070 4765,3070 4765,2640 4415,2640 4220,2445 4220,1800
  text "GND PLANE LAYER" at 6041,1991 h80
  text "3" at 6691,1861 h80

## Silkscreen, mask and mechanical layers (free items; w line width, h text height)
Top Overlay:
  rectangle: 4105,3655 4800,3795
  text "PI3HDMI511ZLE_HDMI ReDriver_EVB" at 4000,3980 h60
  text "P/N:PI3HDMI511ZLE_HDMI CONN_EVB" at 4000,3905 h60
  text "REV.B" at 4000,3835 h60
  text "Date:2012.6.28" at 4400,3835 h60
  text "S/N:" at 4000,3720 h60
  text "OC_S0" at 3765,3660 h60 r270
  text "ROUT_S0" at 3815,3660 h60 r270
  text "EQ_S0" at 3710,3600 h60 r270
  text "OE#" at 3870,3600 h60 r270
  text "SDA_SINK" at 4360,3080 h60 r270
  text "SCL_SINK" at 4160,3075 h60 r270
  text "SDA_SRC" at 3415,3040 h60 r270
  text "SCL_SRC" at 3620,3040 h60 r270
  text "+5V" at 3425,2375 h60
  text "TOP SILKSCREEN LAYER" at 6041,1991 h80
  text "5" at 6691,1861 h80
Bottom Overlay:
  text "BOTTOM SILKSCREEN LAYER" at 6041,1991 h80
  text "1228DB191" at 4825,1870 h60
  text "6" at 6691,1861 h80
Top Paste:
  text "TOP PASTE LAYER" at 6041,1991 h80
  text "TOP PASTE LAYER" at 6041,1991 h80
  text "TP" at 6671,1861 h80
Bottom Paste:
  text "BOTTOM PASTE LAYER" at 6041,1991 h80
  text "BOTTOM PASTE LAYER" at 6041,1991 h80
  text "BP" at 6671,1861 h80
Top Solder:
  text "TOP SOLDER LAYER" at 6041,1991 h80
  text "7" at 6691,1861 h80
Bottom Solder:
  text "BOTTOM SOLDER LAYER" at 6041,1991 h80
  text "8" at 6691,1861 h80
Drill Guide:
  text "DRILL GUIDE LAYER" at 6041,1991 h80
  text "10" at 6671,1861 h80
Mechanical 1:
  lines w7.99: 4800,1800 ccw(c4800,2000) 5000,2000 ; 4800,4300 cw(c4800,4100) 5000,4100
  lines w8: 4800,1800 3300,1800 3300,2519 3116,2703 2780,2703 2702,2781 2702,2896 2800,2896 2800,3453 2702,3453 2702,3569 2781,3648 3115,3648 3300,3833 3300,4300 4800,4300 ; 5000,2000 5000,4100
  lines w10: 6011,1951 6011,2341 ; 6411,1821 6411,1951 ; 6411,2081 6411,2211 ; 6941,2081 6941,2211
  lines w12: 5491,1951 7871,1951 ; 5491,2081 7871,2081 ; 5491,2211 7871,2211 ; 5491,2341 7871,2341 ; 5491,2401 5941,2401 ; 5491,2451 5851,2451 ; 5491,2501 5941,2501 ; 7031,2401 7806,2401 ; 7031,2501 7816,2501 ; 7121,2451 7741,2451
  lines w15: 5491,1821 5491,2571 7871,2571 7871,1821 5491,1821
  text "Pericom" at 6171,2401 h180
  text "PCB NAME" at 5531,2251 h60
  text "PI3HDMI511ZLE_HDMI ReDriver_EVB" at 6041,2251 h80
  text "REV.B" at 7500,2250 h80
  text "DATE" at 5621,2121 h60
  text "6/28/2012" at 6031,2121 h80
  text "Drawn by" at 6441,2121 h60
  text "Haojie Ci" at 7051,2121 h80
  text "TITLE" at 5601,1991 h60
  text "SHEET NUMBER" at 5611,1861 h60
  text "OF       10" at 6911,1861 h80
Drill Drawing:
  lines w10: 5958,3318 5958,3808 ; 6028,2688 6238,2688 ; 6028,3028 6238,3028 ; 6108,2748 6128,2688 ; 6108,2968 6128,3028 ; 6128,2798 6128,2688 ; 6128,2918 6128,3028 ; 6148,2748 6128,2688 ; 6148,2968 6128,3028 ; 6348,3318 6348,3808 ; 7258,3318 7258,3808 ; 8388,3318 8388,3808 ; 6328,2688 7368,2688 7368,2738 6328,2738 6328,2688 ; 6328,2882 7368,2882 7368,2932 6328,2932 6328,2882 ; 6328,2978 6328,3028 7368,3028 7368,2978 6328,2978 ; 6330,2792 6330,2842 7370,2842 7370,2792 6330,2792
  lines w12: 5468,3448 8988,3448 ; 5468,3578 8988,3578
  lines w15: 5468,3318 8988,3318 8988,3808 5468,3808 5468,3318
  text "IMPEDANCE CHART" at 5468,3838 h100
  text "TRACE" at 6018,3698 h60
  text "SINGLE-ENDED" at 6368,3698 h60
  text "DIFFERENTIAL-ENDED" at 7308,3698 h60
  text "LAYER(S)" at 5508,3658 h60
  text "TOLERANCE" at 8428,3658 h60
  text "TYPE" at 6018,3618 h60
  text "IMPEDANCE REQ'D" at 6368,3618 h60
  text "IMPEDANCE REQ'D" at 7308,3618 h60
  text "+/- 10%" at 8568,3498 h80
  text "1" at 5698,3488 h80
  text "--" at 6143,3488 h80
  text "--" at 6748,3488 h80
  text "--" at 7788,3488 h80
  text "9/10/9mil" at 6005,3359 h80
  text "1" at 5698,3358 h80
  text "--" at 6748,3358 h80
  text "100ohm" at 7688,3358 h80
  text "+/- 10%" at 8568,3358 h80
  text "LAYER1 SIGNAL" at 7408,2978 h80
  text "LAYER2 GROUND PLANE" at 7409,2875 h80
  text "THICKNESS is 1.6mm" at 5508,2838 h80
  text "LAYER3 PWR PLANE" at 7409,2786 h80
  text "LAYER4 SIGNAL" at 7408,2688 h80
  text "DRILL DRAWING LAYER" at 6041,1991 h80
  text "9" at 6691,1861 h80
